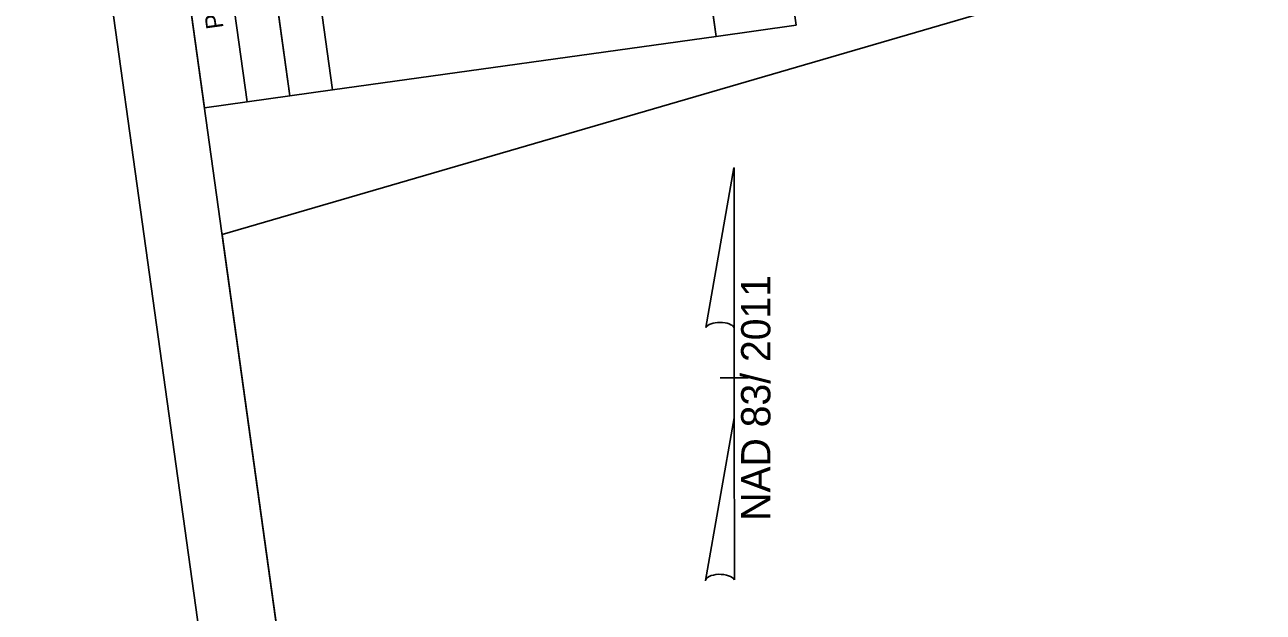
# Model space of a CAD drawing. Extents: x 477288 to 478604, y 497629 to 499448.
# Drawn here: x 477287.6 to 477647.3, y 498938.2 to 499108.8 of the extents above; entities that cross this region are included whole.
import ezdxf

# ---------------------------------------------------------------- set-up
doc = ezdxf.new("R2010")
doc.units = 0
for name, color, linetype in [('Prop North Arrow NAD83 for Plan Sheets CELL', 7, 'Continuous'), ('Sheet Clip Boundary CELL', 7, 'Continuous'), ('Sheet Plan CELL', 7, 'Continuous'), ('Sheet Plot Border Outside CELL', 7, 'Continuous'), ('Sheet Sticker Exception Certification CELL', 7, 'Continuous')]:
    doc.layers.add(name, color=color, linetype=linetype)

msp = doc.modelspace()

# ---------------------------------------------------------------- linework, layer by layer
at = {"layer": 'Prop North Arrow NAD83 for Plan Sheets CELL'}
for p, q in [((477485.4, 499020.9), (477493.6, 499067.25)), ((477493.65, 499067.25), (477493.6, 499067.25)), ((477493.65, 499067.25), (477493.6, 499067.25)), ((477493.65, 499067.25), (477493.65, 499019.45)), ((477493.65, 498994.65), (477493.65, 499020.85)), ((477493.65, 499019.45), (477493.65, 499020.8)), ((477489.65, 499006.25), (477489.6, 499006.25)), ((477493.2, 499006.25), (477489.65, 499006.25)), ((477489.7, 499006.25), (477497.7, 499006.25)), ((477493.65, 498994.65), (477485.3, 498947.4)), ((477493.7, 498947.6), (477493.65, 498994.65))]:
    msp.add_line(p, q, dxfattribs=at)
for centre, start_param, end_param in [((477489.53, 499020.41), 0.216388, 2.908219), ((477489.53, 498947.24), 0.201328, 3.141593)]:
    msp.add_ellipse(centre, major_axis=(4.23, -0.03), ratio=0.461098, start_param=start_param, end_param=end_param, dxfattribs=at)
at = {"layer": 'Sheet Clip Boundary CELL'}
msp.add_lwpolyline([(477503.45, 497908.53), (477747.98, 497967.8), (478463.84, 498067.43), (478543.42, 498053.26), (478416.48, 498965.45), (478367.57, 498958.64), (478326.76, 499251.85), (478296.42, 499247.63), (478286.21, 499322.33), (478005.32, 499240.42), (477344.89, 499047.85)], close=True, dxfattribs=at)
at = {"layer": 'Sheet Plan CELL'}
for p, q in [((477352.18, 499086.44), (477324.62, 499284.58)), ((477364.6, 499088.18), (477337, 499286.31)), ((477364.6, 499088.18), (477337, 499286.31)), ((477364.6, 499088.18), (477376.97, 499089.9))]:
    msp.add_line(p, q, dxfattribs=at)
for points in [[(477312.18, 499282.89), (477518.94, 497797.17), (478558.92, 497941.9), (478352.17, 499427.6)], [(477339.75, 499084.72), (477312.18, 499282.89), (477337, 499286.31), (477364.6, 499088.18)], [(477376.97, 499089.9), (477363.18, 499189), (477474.61, 499204.51), (477488.38, 499105.42)]]:
    msp.add_lwpolyline(points, close=True, dxfattribs=at)
at = {"layer": 'Sheet Plot Border Outside CELL'}
msp.add_lwpolyline([(478604.17, 497780.1), (478372.12, 499447.54), (477287.57, 499296.6), (477519.62, 497629.17)], close=True, dxfattribs=at)
at = {"layer": 'Sheet Sticker Exception Certification CELL'}
for p, q in [((477484.08, 499306.79), (477511.65, 499108.66)), ((477484.08, 499306.79), (477511.65, 499108.66)), ((477488.38, 499105.42), (477460.81, 499303.55)), ((477488.38, 499105.42), (477460.81, 499303.55)), ((477511.65, 499108.66), (477488.38, 499105.42)), ((477511.65, 499108.66), (477488.38, 499105.42))]:
    msp.add_line(p, q, dxfattribs=at)

# ---------------------------------------------------------------- texts
at = {"layer": 'Prop North Arrow NAD83 for Plan Sheets CELL'}
msp.add_text('NAD 83/ 2011', height=8.5, rotation=90, dxfattribs=at).set_placement((477504.17, 498964.73))
at = {"layer": 'Sheet Plan CELL'}
msp.add_text('PROJECT REFERENCE NO.', height=5.0001, rotation=97.9227, dxfattribs=at).set_placement((477345.33, 499107.92))

doc.saveas('drawing.dxf')
